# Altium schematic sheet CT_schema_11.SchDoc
size 210 x 185 mm
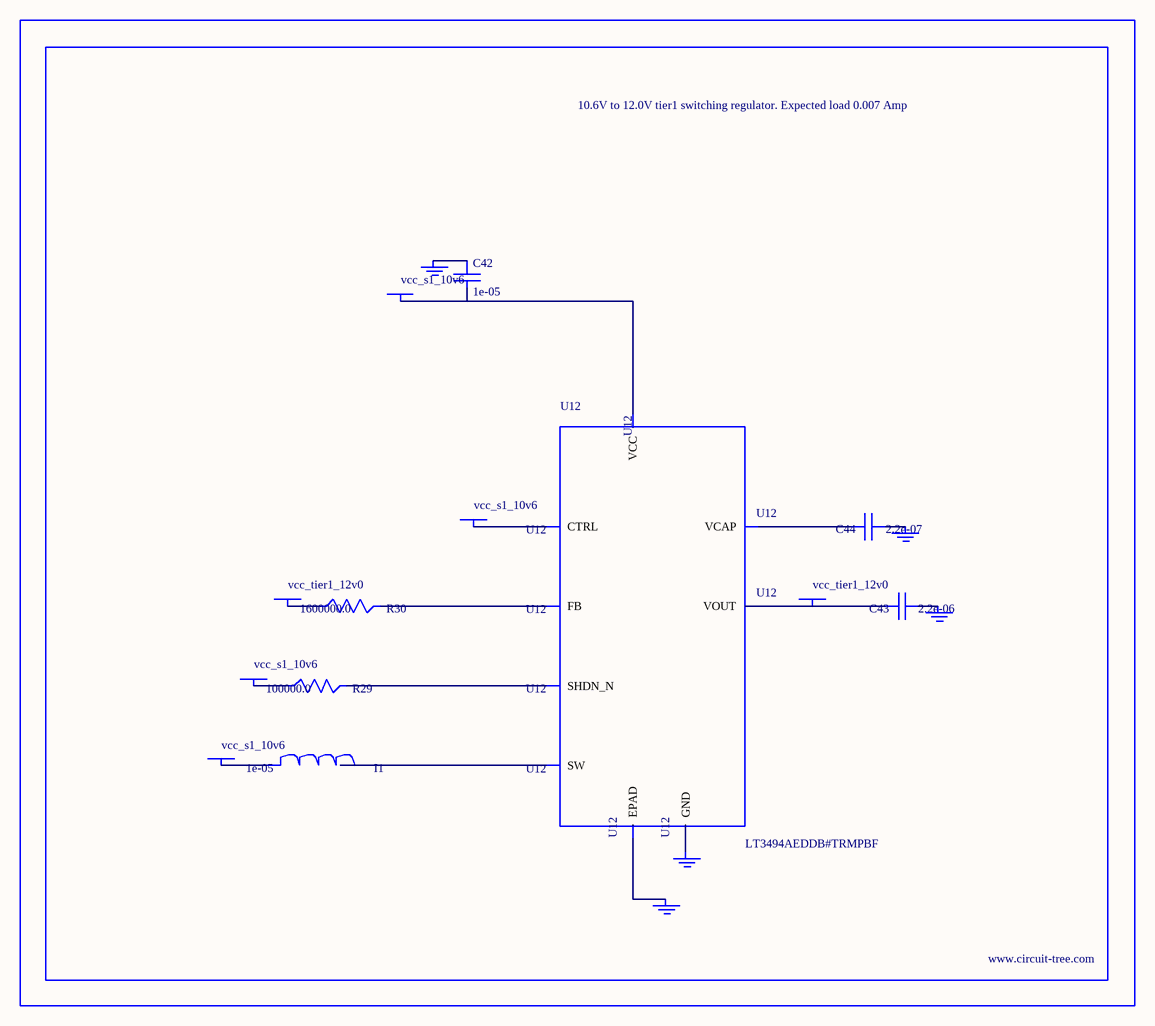
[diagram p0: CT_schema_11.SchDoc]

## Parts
BORDER10  (no value)
C42  1e-05  [C1210]
C43  2.2e-06  [C0603]
C44  2.2e-07  [C0603]
GND_INSTANCE_10_0  (no value)
GND_INSTANCE_10_1  (no value)
GND_INSTANCE_10_2  (no value)
GND_INSTANCE_10_3  (no value)
GND_INSTANCE_10_4  (no value)
I1  1e-05  [L1210]
POWER_INSTANCE_10_0  vcc_s1_10v6
POWER_INSTANCE_10_1  vcc_s1_10v6
POWER_INSTANCE_10_2  vcc_s1_10v6
POWER_INSTANCE_10_3  vcc_s1_10v6
POWER_INSTANCE_10_4  vcc_tier1_12v0
POWER_INSTANCE_10_5  vcc_tier1_12v0
R29  100000.0  [R0603]
R30  1600000.0  [R0603]
U12  LT3494AEDDB#TRMPBF  [DFN-8_DDB]

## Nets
NetC42_1: C42.1 GND_INSTANCE_10_0.0(GND)
NetC42_2: C42.2 POWER_INSTANCE_10_1.0(PWR) U12.3(VCC)
NetC43_1: C43.1 GND_INSTANCE_10_1.0(GND)
NetC43_2: C43.2 POWER_INSTANCE_10_5.0(PWR) U12.7(VOUT)
NetC44_1: C44.1 GND_INSTANCE_10_2.0(GND)
NetC44_2: C44.2 U12.8(VCAP)
NetGND_INSTANCE_10_3_0: GND_INSTANCE_10_3.0(GND) U12.9(EPAD)
NetGND_INSTANCE_10_4_0: GND_INSTANCE_10_4.0(GND) U12.2(GND)
NetI1_1: I1.1 POWER_INSTANCE_10_0.0(PWR)
NetI1_2: I1.2 U12.1(SW)
NetPOWER_INSTANCE_10_2_0: POWER_INSTANCE_10_2.0(PWR) U12.4(CTRL)
NetPOWER_INSTANCE_10_3_0: POWER_INSTANCE_10_3.0(PWR) R29.1
NetPOWER_INSTANCE_10_4_0: POWER_INSTANCE_10_4.0(PWR) R30.1
NetR29_2: R29.2 U12.5(SHDN_N)
NetR30_2: R30.2 U12.6(FB)

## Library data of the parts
BORDER10 = BORDER_PAGE10
C42 = C1210C106K5PACTU
C43 = GRM188R61H225KE1115D
C44 = C0603C224K3RAC
GND_INSTANCE_10_0-GND_INSTANCE_10_4 = GND
I1 = CBC3225T100MR
POWER_INSTANCE_10_0-POWER_INSTANCE_10_5 = PWR
R29 = RC0603JR-07100KL
R30 = RC0603JR-071M6L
